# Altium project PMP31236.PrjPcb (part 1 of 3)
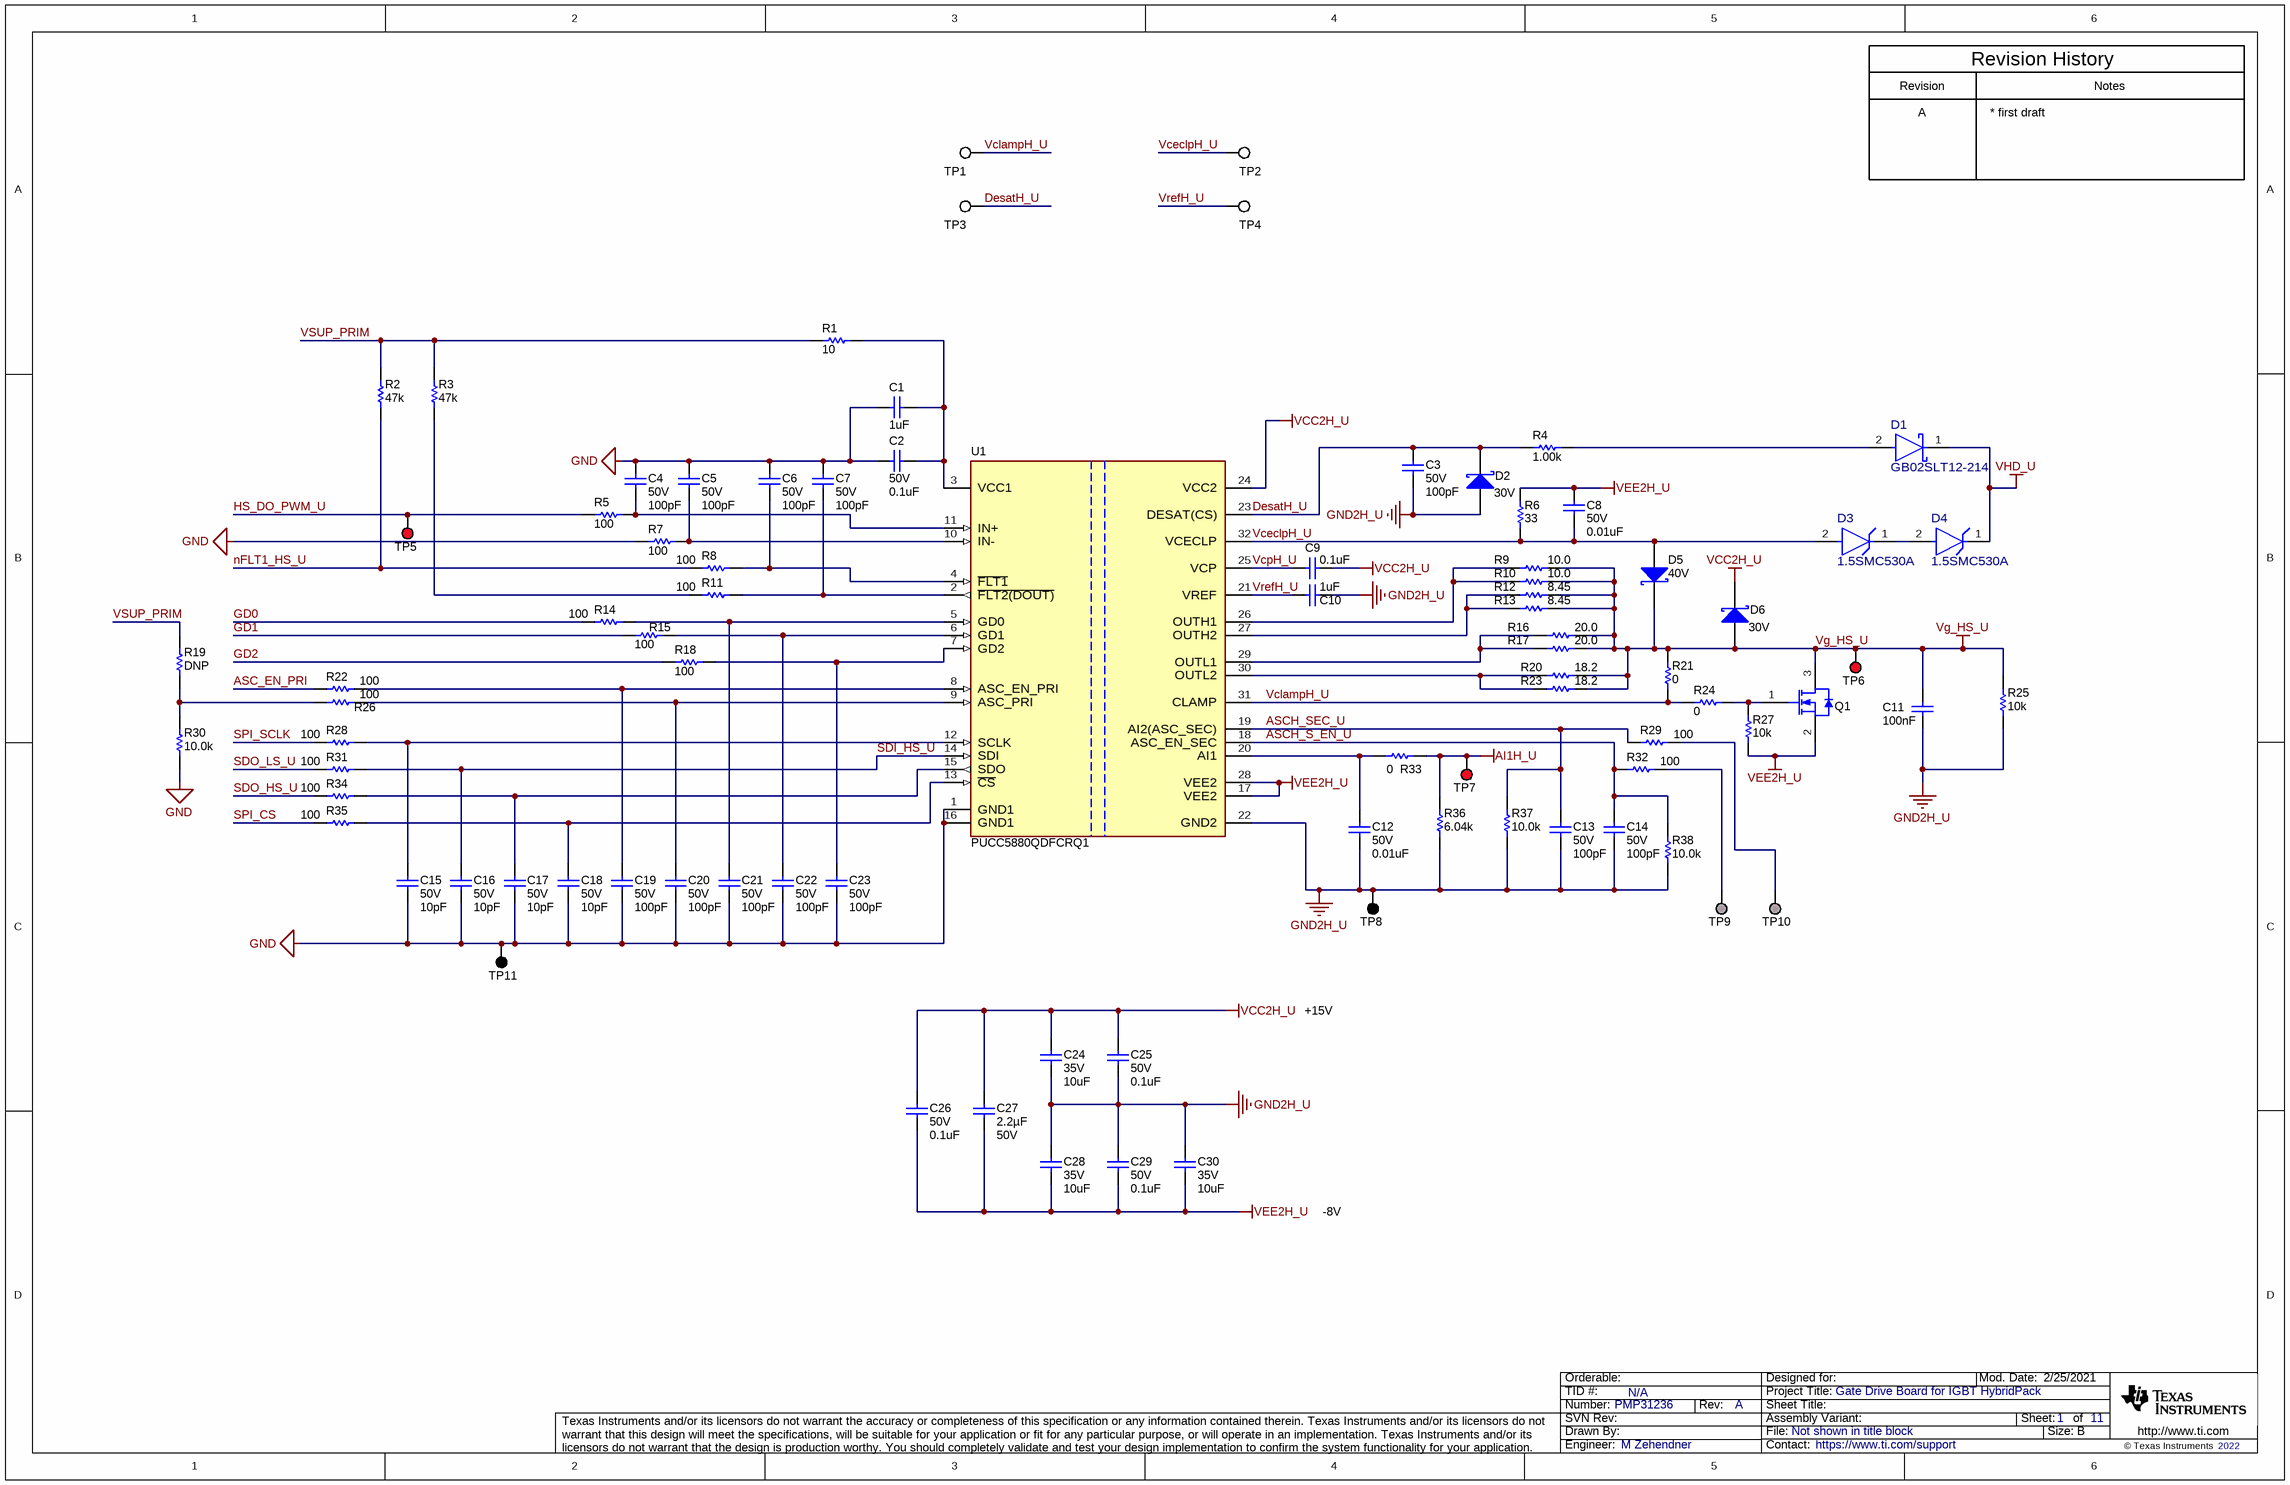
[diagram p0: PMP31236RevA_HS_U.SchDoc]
CopyrightYear: 2022; PRJ_Engineer: M Zehendner; PRJ_Number: PMP31236; PRJ_Title: Gate Drive Board for IGBT HybridPack; SCH_Rev: A; TechSupport: https://www.ti.com/support; TID: N/A
11 sheets, 732 parts. Net scope: global (net labels, ports and power ports of the same name join across sheets).
Board file: PMP31236.PcbDoc
Sheets:
  PMP31236RevA_HS_U.SchDoc
  PMP31236RevA_HS_V.SchDoc
  PMP31236RevA_HS_W.SchDoc
  PMP31236RevA_LS_U.SchDoc
  PMP31236RevA_LS_V.SchDoc
  PMP31236RevA_LS_W.SchDoc
  PMP31236RevA_Interface.SchDoc
  PMP31236RevA_Supply_U.SchDoc
  PMP31236RevA_Supply_V.SchDoc
  PMP31236RevA_Supply_W.SchDoc
  PMP31236RevA_IGBT_Module.SchDoc

## Sheet PMP31236RevA_HS_U.SchDoc
size 431 x 279 mm; Date: Not shown in title block; ApprovedBy: Not shown in title block; CheckedBy: Not shown in title block; Author: Not shown in title block; CompanyName: Not shown in title block; Engineer: Not shown in title block; Organization: Not shown in title block; Address1: Not shown in title block; Address2: Not shown in title block; Address3: Not shown in title block; Address4: Not shown in title block; DocumentNumber: 1; Revision: Use project parameter SCH_Rev; SheetNumber: 1; SheetTotal: 11; PageSetup: Record=PageOptions¦CenterHorizontal=True¦CenterVertical=True¦PrintScale=1.00¦XCorrection=1.00¦YCorrection=1.00¦PrintKind=0¦BorderSize=5000000¦LeftOffset=0¦BottomOffset=0¦Orientation=2¦PaperLength=1000¦PaperWidth=1000¦Scale=100¦PaperSource=15¦PrintQuality=600¦MediaType=1¦DitherType=10¦PaperKind=Letter¦PrintScaleMode=1

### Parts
C1  ValueDisplayed: 1uF  [0603]  (hidden comment: GRM21BR72A104KAC4L)
C2  VDC_V: 50V  ValueDisplayed: 0.1uF  [0402]  (hidden comment: GCM155R71H104KE02D)
C3  VDC_V: 50V  ValueDisplayed: 100pF  [0402]  (hidden comment: GRM1555C1H101JA01D)
C4  VDC_V: 50V  ValueDisplayed: 100pF  [0402]  (hidden comment: GRM1555C1H101JA01D)
C5  VDC_V: 50V  ValueDisplayed: 100pF  [0402]  (hidden comment: GRM1555C1H101JA01D)
C6  VDC_V: 50V  ValueDisplayed: 100pF  [0402]  (hidden comment: GRM1555C1H101JA01D)
C7  VDC_V: 50V  ValueDisplayed: 100pF  [0402]  (hidden comment: GRM1555C1H101JA01D)
C8  VDC_V: 50V  ValueDisplayed: 0.01uF  [0402]  (hidden comment: CGA2B3X7R1H103K050BB)
C9  ValueDisplayed: 0.1uF  [0402]  (hidden comment: GCM155R71H104KE02D)
C10  ValueDisplayed: 1uF  [0603]  (hidden comment: CGA3E1X7R1V105K080AC)
C11  Cap_F: 100nF  [0805_HV]  (hidden comment: C0805C104K5RACAUTO)
C12  VDC_V: 50V  ValueDisplayed: 0.01uF  [0402]  (hidden comment: CGA2B3X7R1H103K050BB)
C13  VDC_V: 50V  ValueDisplayed: 100pF  [0402]  (hidden comment: GRM1555C1H101JA01D)
C14  VDC_V: 50V  ValueDisplayed: 100pF  [0402]  (hidden comment: GRM1555C1H101JA01D)
C15  VDC_V: 50V  ValueDisplayed: 10pF  [0402]  (hidden comment: GCM1555C1H100JA16D)
C16  VDC_V: 50V  ValueDisplayed: 10pF  [0402]  (hidden comment: GCM1555C1H100JA16D)
C17  VDC_V: 50V  ValueDisplayed: 10pF  [0402]  (hidden comment: GCM1555C1H100JA16D)
C18  VDC_V: 50V  ValueDisplayed: 10pF  [0402]  (hidden comment: GCM1555C1H100JA16D)
C19  VDC_V: 50V  ValueDisplayed: 100pF  [0402]  (hidden comment: GRM1555C1H101JA01D)
C20  VDC_V: 50V  ValueDisplayed: 100pF  [0402]  (hidden comment: GRM1555C1H101JA01D)
C21  VDC_V: 50V  ValueDisplayed: 100pF  [0402]  (hidden comment: GRM1555C1H101JA01D)
C22  VDC_V: 50V  ValueDisplayed: 100pF  [0402]  (hidden comment: GRM1555C1H101JA01D)
C23  VDC_V: 50V  ValueDisplayed: 100pF  [0402]  (hidden comment: GRM1555C1H101JA01D)
C24  VDC_V: 35V  ValueDisplayed: 10uF  [1206_190]  (hidden comment: CGA5L1X7R1V106M160AC)
C25  VDC_V: 50V  ValueDisplayed: 0.1uF  [0402]  (hidden comment: GCM155R71H104KE02D)
C26  VDC_V: 50V  ValueDisplayed: 0.1uF  [0402]  (hidden comment: GCM155R71H104KE02D)
C27  Cap_F: 2.2µF  VDC_V: 50V  [0805_HV]  (hidden comment: CGA4J3X7R1H225K125AB)
C28  VDC_V: 35V  ValueDisplayed: 10uF  [1206_190]  (hidden comment: CGA5L1X7R1V106M160AC)
C29  VDC_V: 50V  ValueDisplayed: 0.1uF  [0402]  (hidden comment: GCM155R71H104KE02D)
C30  VDC_V: 35V  ValueDisplayed: 10uF  [1206_190]  (hidden comment: CGA5L1X7R1V106M160AC)
D1  GB02SLT12-214  [FP-GB02SLT12-214_DO-214AA-MFG]
D2  value 30V  [SOD-323]  (hidden comment: BAT54WS-7-F)
D3  1.5SMC530A  [FP-1.5SMC530A_SMC-MFG]
D4  1.5SMC530A  [FP-1.5SMC530A_SMC-MFG]
D5  value 40V  [SMA]  (hidden comment: MBRA340T3G)
D6  value 30V  [SOD-323]  (hidden comment: BAT54WS-7-F)
Q1  SI2318CDS-T1-GE3  [SOT-23]  (value not drawn)
R1  ValueDisplayed: 10  [0402]  (hidden comment: CRCW040210R0JNED)
R2  ValueDisplayed: 47k  [0402]  (hidden comment: CRCW040247K0JNED)
R3  ValueDisplayed: 47k  [0402]  (hidden comment: CRCW040247K0JNED)
R4  ValueDisplayed: 1.00k  [0603]  (hidden comment: CRCW06031K00FKEA)
R5  ValueDisplayed: 100  [0402]  (hidden comment: CRCW0402100RJNED)
R6  ValueDisplayed: 33  [0603]  (hidden comment: CRCW060333R0JNEA)
R7  ValueDisplayed: 100  [0402]  (hidden comment: CRCW0402100RJNED)
R8  ValueDisplayed: 100  [0402]  (hidden comment: CRCW0402100RJNED)
R9  ValueDisplayed: 10.0  [0805_HV]  (hidden comment: CRCW080510R0FKEA)
R10  ValueDisplayed: 10.0  [0805_HV]  (hidden comment: CRCW080510R0FKEA)
R11  ValueDisplayed: 100  [0402]  (hidden comment: CRCW0402100RJNED)
R12  ValueDisplayed: 8.45  [0805_HV]  (hidden comment: CRCW08058R45FKEA)
R13  ValueDisplayed: 8.45  [0805_HV]  (hidden comment: CRCW08058R45FKEA)
R14  ValueDisplayed: 100  [0402]  (hidden comment: CRCW0402100RJNED)
R15  ValueDisplayed: 100  [0402]  (hidden comment: CRCW0402100RJNED)
R16  ValueDisplayed: 20.0  [0805_HV]  (hidden comment: CRCW080520R0FKEA)
R17  ValueDisplayed: 20.0  [0805_HV]  (hidden comment: CRCW080520R0FKEA)
R18  ValueDisplayed: 100  [0402]  (hidden comment: CRCW0402100RJNED)
R19  ValueDisplayed: DNP  [0402]  (hidden comment: CRCW040210K0FKED)
R20  ValueDisplayed: 18.2  [0805_HV]  (hidden comment: CRCW080518R2FKEA)
R21  ValueDisplayed: 0  [0603]  (hidden comment: CRCW06030000Z0EA)
R22  ValueDisplayed: 100  [0402]  (hidden comment: CRCW0402100RJNED)
R23  ValueDisplayed: 18.2  [0805_HV]  (hidden comment: CRCW080518R2FKEA)
R24  ValueDisplayed: 0  [0603]  (hidden comment: CRCW06030000Z0EA)
R25  ValueDisplayed: 10k  [0603]  (hidden comment: CRCW060310K0JNEA)
R26  ValueDisplayed: 100  [0402]  (hidden comment: CRCW0402100RJNED)
R27  ValueDisplayed: 10k  [0603]  (hidden comment: CRCW060310K0JNEA)
R28  ValueDisplayed: 100  [0402]  (hidden comment: CRCW0402100RJNED)
R29  ValueDisplayed: 100  [0402]  (hidden comment: CRCW0402100RFKED)
R30  ValueDisplayed: 10.0k  [0402]  (hidden comment: CRCW040210K0FKED)
R31  ValueDisplayed: 100  [0402]  (hidden comment: CRCW0402100RJNED)
R32  ValueDisplayed: 100  [0402]  (hidden comment: CRCW0402100RFKED)
R33  ValueDisplayed: 0  [0402]  (hidden comment: CRCW04020000Z0ED)
R34  ValueDisplayed: 100  [0402]  (hidden comment: CRCW0402100RJNED)
R35  ValueDisplayed: 100  [0402]  (hidden comment: CRCW0402100RJNED)
R36  ValueDisplayed: 6.04k  [0402]  (hidden comment: CRCW04026K04FKED)
R37  ValueDisplayed: 10.0k  [0402]  (hidden comment: CRCW040210K0FKED)
R38  ValueDisplayed: 10.0k  [0402]  (hidden comment: CRCW040210K0FKED)
TP1  (no value)  [Keystone5002]
TP2  (no value)  [Keystone5002]
TP3  (no value)  [Keystone5002]
TP4  (no value)  [Keystone5002]
TP5  5000  [Keystone5000]  (value not drawn)
TP6  5000  [Keystone5000]  (value not drawn)
TP7  5000  [Keystone5000]  (value not drawn)
TP8  5001  [Keystone5001]  (value not drawn)
TP9  TP_SM_1MM  [TP_SM_1MM]  (value not drawn)  (no BOM)
TP10  TP_SM_1MM  [TP_SM_1MM]  (value not drawn)  (no BOM)
TP11  5001  [Keystone5001]  (value not drawn)
U1  PUCC5880QDFCRQ1  [DFC0032A-MFG]

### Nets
AI1H_U: R33.2 R36.2 TP7.1
GND: C1.2 C2.1 C4.1 C5.1 C6.1 C7.1 C15.2 C16.2 C17.2 C18.2 C19.2 C20.2 C21.2 C22.2 C23.2 R7.1 R30.1 TP11.1 U1.1(GND1) U1.16(GND1)
GND2H_U: C3.2 C10.2 C11.2 C12.2 C13.2 C14.2 C24.2 C25.2 C28.1 C29.1 C30.1 D2.2(A) R25.1 R36.1 R37.1 R38.1 TP8.1 U1.22(GND2)
VCC2H_U: C9.2 C24.1 C25.1 C26.1 C27.1 D6.1(K) U1.24(VCC2)
VEE2H_U: C8.1 C26.2 C27.2 C28.2 C29.2 C30.2 Q1.2(S) R6.2 R27.1 U1.17(VEE2) U1.28(VEE2)
Vg_HS_U: C11.1 D5.1(K) D6.2(A) Q1.3(D) R9.2 R10.2 R12.2 R13.2 R16.2 R17.2 R20.2 R21.2 R23.2 R25.2 TP6.1
VHD_U: D1.1(CATHODE) D4.1(CATHODE)
ASC_EN_PRI: R22.1
ASCH_S_EN_U: C14.1 R32.1 R38.2 U1.18(ASC_EN_SEC)
ASCH_SEC_U: C13.1 R29.1 R37.2 U1.19(AI2(ASC_SEC))
DesatH_U: C3.1 D2.1(K) R4.1 TP3.1 U1.23(DESAT(CS))
GD0: R14.1
GD1: R15.1
GD2: R18.1
HS_DO_PWM_U: R5.1 TP5.1
nFLT1_HS_U: R2.1 R8.1
SDI_HS_U: C16.1 R31.2 U1.14(SDI)
SDO_HS_U: R34.1
SDO_LS_U: R31.1
SPI_CS: R35.1
SPI_SCLK: R28.1
VceclpH_U: C8.2 D3.2(ANODE) D5.2(A) R6.1 TP2.1 U1.32(VCECLP)
VclampH_U: R21.1 R24.2 TP1.1 U1.31(CLAMP)
VcpH_U: C9.1 U1.25(VCP)
VrefH_U: C10.1 TP4.1 U1.21(VREF)
VSUP_PRIM: R1.1 R2.2 R3.2 R19.2
NetC1_1: C1.1 C2.2 R1.2 U1.3(VCC1)
NetC4_2: C4.2 R5.2 U1.11(IN+)
NetC5_2: C5.2 R7.2 U1.10(IN-)
NetC6_2: C6.2 R8.2 U1.4(~{FLT1})
NetC7_2: C7.2 R11.2 U1.2(~{FLT2(DOUT)})
NetC12_1: C12.1 R33.1 U1.20(AI1)
NetC15_1: C15.1 R28.2 U1.12(SCLK)
NetC17_1: C17.1 R34.2 U1.15(SDO)
NetC18_1: C18.1 R35.2 U1.13(~{CS})
NetC19_1: C19.1 R22.2 U1.8(ASC_EN_PRI)
NetC20_1: C20.1 R26.2 U1.9(ASC_PRI)
NetC21_1: C21.1 R14.2 U1.5(GD0)
NetC22_1: C22.1 R15.2 U1.6(GD1)
NetC23_1: C23.1 R18.2 U1.7(GD2)
NetD1_2: D1.2(ANODE) R4.2
NetD3_1: D3.1(CATHODE) D4.2(ANODE)
NetQ1_1: Q1.1(G) R24.1 R27.2
NetR3_1: R3.1 R11.1
NetR9_1: R9.1 R10.1 U1.26(OUTH1)
NetR12_1: R12.1 R13.1 U1.27(OUTH2)
NetR16_1: R16.1 R17.1 U1.29(OUTL1)
NetR19_1: R19.1 R26.1 R30.2
NetR20_1: R20.1 R23.1 U1.30(OUTL2)
NetR29_2: R29.2 TP10.1
NetR32_2: R32.2 TP9.1

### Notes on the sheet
- Revision
- Revision History
- Notes
- A
- * first draft
- +15V
- -8V

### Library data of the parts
C1 = CMP-0007067-4: CAP, CERM, 1 uF, 35 V, +/- 10%, X7R, AEC-Q200 Grade 1, 0603; Manufacturer: TDK; PartNumber: CGA3E1X7R1V105K080AC; TaMin_C: -55°C; ESR_ohm: 5.522m; Polarized: N; SizeAreaWB_mm2: 4.68; Value1: 0.005522 ohm; U/M: EA; Value: 1uF; TaMax_C: 125°C; SizeZ_mm: 1; SizeX_mm: 1.6; SizeY_mm: 0.8; Value2: 35V; SizeArea_mm2: 1.28; CompType: Capacitor; AEC Qualified: Y; Cap_F: 1µF; IRMS_A: 2.21617A; AEC Category: Q200
C2 C25 C26 C29 = CMP-0006356-2: CAP, CERM, 0.1 uF, 50 V, +/- 10%, X7R, AEC-Q200 Grade 1, 0402; Manufacturer: MuRata; TaMin_C: -55°C; Polarized: N; SizeAreaWB_mm2: 3; Value1: Unknown; U/M: EA; Value: 0.1uF; TaMax_C: 125°C; SizeZ_mm: 0.6; SizeX_mm: 1; SizeY_mm: 0.5; AEC Qualified: Y; Cap_F: 100nF; AEC Category: Q200
C3-C7 C13 C14 C19-C23 = CMP-0006410-2: CAP, CERM, 100 pF, 50 V, +/- 5%, C0G/NP0, 0402; Manufacturer: MuRata; TaMin_C: -55°C; Polarized: N; SizeAreaWB_mm2: 3; Value1: Unknown; U/M: EA; Value: 100pF; TaMax_C: 125°C; SizeZ_mm: 0.6; SizeX_mm: 1; SizeY_mm: 0.5; AEC Category: Q200
C8 C12 = CMP-0006324-2: CAP, CERM, 0.01 uF, 50 V, +/- 10%, X7R, AEC-Q200 Grade 1, 0402; Manufacturer: TDK; TaMin_C: -55°C; ESR_ohm: 0.3331; Polarized: N; SizeAreaWB_mm2: 3; Value1: 0.333065 ohm; U/M: EA; Value: 0.01uF; TaMax_C: 125°C; SizeZ_mm: 0.6; SizeX_mm: 1; SizeY_mm: 0.5; AEC Qualified: Y; Cap_F: 10nF; IRMS_A: 323.373mA; AEC Category: Q200
C9 = CMP-0006356-2: CAP, CERM, 0.1 uF, 50 V, +/- 10%, X7R, AEC-Q200 Grade 1, 0402; Manufacturer: MuRata; TaMin_C: -55°C; Polarized: N; SizeAreaWB_mm2: 3; Value1: Unknown; U/M: EA; Value: 0.1uF; TaMax_C: 125°C; SizeZ_mm: 0.6; SizeX_mm: 1; SizeY_mm: 0.5; Value2: 50V; AEC Qualified: Y; Cap_F: 100nF; AEC Category: Q200
C10 = CMP-0007067-4: CAP, CERM, 1 uF, 35 V, +/- 10%, X7R, AEC-Q200 Grade 1, 0603; Manufacturer: TDK; TaMin_C: -55°C; ESR_ohm: 5.522m; Polarized: N; SizeAreaWB_mm2: 4.68; Value1: 0.005522 ohm; U/M: EA; Value: 1uF; TaMax_C: 125°C; SizeZ_mm: 1; SizeX_mm: 1.6; SizeY_mm: 0.8; Value2: 35V; SizeArea_mm2: 1.28; CompType: Capacitor; AEC Qualified: Y; Cap_F: 1µF; IRMS_A: 2.21617A; AEC Category: Q200
C11 = CMP-0007725-2: CAP, CERM, 0.1 uF, 50 V, +/- 10%, X7R, AEC-Q200 Grade 0, 0805; Manufacturer: Kemet; TaMin_C: -55°C; Polarized: N; SizeAreaWB_mm2: 6.75; Value1: Unknown; U/M: EA; Value: 0.1uF; TaMax_C: 125°C; SizeZ_mm: 1.45; SizeX_mm: 2; SizeY_mm: 1.25; Cap_Case: 0805; Value2: 50V; SizeArea_mm2: 2.5; AEC Qualified: Y; AEC Grade: 0; AEC Category: Q200
C15-C18 = CMP-0860290-1: CAP, CERM, 10 pF, 50 V,+/- 5%, C0G/NP0, AEC-Q200 Grade 1, 0402; Manufacturer: MuRata; TaMin_C: -55°C; AEC Grade: 1; AEC Qualified: Y; SizeAreaWB_mm2: 3; SizeZ_mm: 0.6; Value: 10pF; TaMax_C: 125°C; Polarized: N; SizeArea_mm2: 0.5; U/M: EA; AEC Category: Q200
C24 C28 C30 = CMP-0008772-2: CAP, CERM, 10 uF, 35 V, +/- 10%, X7R, AEC-Q200 Grade 1, 1206_190; Manufacturer: TDK; PartNumber: CGA5L1X7R1V106K160AC; TaMin_C: -55°C; ESR_ohm: 2.229m; Polarized: N; SizeAreaWB_mm2: 10.92; Value1: 0.002229 ohm; U/M: EA; Value: 10uF; TaMax_C: 125°C; SizeZ_mm: 1.9; SizeX_mm: 3.2; SizeY_mm: 1.6; SizeArea_mm2: 5.12; AEC Qualified: Y; Cap_F: 10µF; IRMS_A: 4.85932A; AEC Grade: 1; AEC Category: Q200
C27 = CMP-0007977-2: CAP, CERM, 2.2 uF, 50 V, +/- 10%, X7R, AEC-Q200 Grade 1, 0805; Manufacturer: TDK; TaMin_C: -55°C; ESR_ohm: 3.288m; Polarized: N; SizeAreaWB_mm2: 6.75; Value1: 0.003288 ohm; U/M: EA; Value: 2.2uF; TaMax_C: 125°C; SizeZ_mm: 1.45; SizeX_mm: 2; SizeY_mm: 1.25; Cap_Case: 0805; SizeArea_mm2: 2.5; AEC Qualified: Y; IRMS_A: 3.6003A; AEC Grade: 1; AEC Category: Q200
D1 = CMP-0095009-1: Diode Silicon Carbide Schottky 1200 V 2A (DC) Surface Mount DO-214AA; Manufacturer: GeneSiC Semiconductor; Max Surge Forward Current: 20A; ValueDisplayed: 122pF; Vf_V: 1.2kV; Peak Reverse Current: 1uA; SizeZ_mm: 2.44mm; AEC Qualified: No; TJmax_C: 175°C
D2 D6 = CMP-0028458-1: Diode, Schottky, 30 V, 0.2 A, SOD-323; Manufacturer: Diodes Inc.; Io_A: 2dA; Green_Lifecycle: Active; SizeAreaWB_mm2: 8.695; Green_REACh: Passed; Value1: 0.2A; TJmax_C: 125°C; U/M: EA; SizeZ_mm: 1; SizeX_mm: 2.7; SizeY_mm: 1.35; Vf_V: 7dV; Value2: 0.7V; SizeArea_mm2: 3.645; AEC Category: Q101
D3 D4 = CMP-0095023-1: 725V Clamp 2.1A Ipp Tvs Diode Surface Mount DO-214AB (SMCJ); Manufacturer: Littelfuse Inc; SizeZ_mm: 2.62mm; Breakdown Voltage: 503.5V; Ppk: 1.5kW; VRWM: 451V; Direction: Unidirectional; AEC Qualified: No; TJmax_C: +150°C; Number Of Channels: 1; Ipp: 2.8A
D5 = CMP-0028553-2: Diode, Schottky, 40 V, 3 A, SMA; Manufacturer: ON Semiconductor; Io_A: 3A; Green_Lifecycle: Not Set; SizeAreaWB_mm2: 37.3428; Green_REACh: Incomplete; SizeZ_mm: 2.87; SizeX_mm: 5.59; SizeY_mm: 2.92; Vf_V: 415mV; Value2: 0.415V; SizeArea_mm2: 16.3228; AEC Category: Q101; RJC_CperW: 15
Q1 = CMP-0000739-1: MOSFET, N-CH, 40 V, 5.6 A, SOT-23; Alternate Manufacturer: None; Manufacturer: Vishay-Siliconix; SizeZ_mm: 1.1; ChType: N; Value2: 5.8 nC; Value1: 0.05; VdsMax_V: 40V; SizeX_mm: 2.5; SizeY_mm: 3; Vgs_V: 20V; Value: 40V; Rdson45_ohm: 0.051; SizeArea_mm2: 7.5; AEC Category: Q101; IdsMax_A: 5.6A; SizeAreaWB_mm2: 14; U/M: EA; QgTyp_nC: 5.8
R1 = CMP-0026827-3: RES, 10, 5%, 0.063 W, AEC-Q200 Grade 0, 0402; Manufacturer: Vishay-Dale; Power_W: 63mW; TempCo: 200 ppm/C; Value_Code: 10R0; Value: 10; EIA_Code: E24; SizeX_mm: 1; SizeY_mm: 0.5; SizeZ_mm: 0.6; Value2: 0.063W; AEC Qualified: Y; VDC_V: 50V; AEC Category: Q200; AEC Grade: 0
R2 R3 = CMP-0026935-3: RES, 47 k, 5%, 0.063 W, AEC-Q200 Grade 0, 0402; Manufacturer: Vishay-Dale; Power_W: 63mW; TempCo: 200 ppm/C; Value_Code: 47k0; Value: 47k; EIA_Code: E24; SizeX_mm: 1; SizeY_mm: 0.5; SizeZ_mm: 0.6; Value2: 0.063W; AEC Qualified: Y; VDC_V: 50V; AEC Category: Q200; AEC Grade: 0
R4 = CMP-0022109-5: RES, 1.00 k, 1%, 0.1 W, AEC-Q200 Grade 0, 0603; Manufacturer: Vishay-Dale; Power_W: 100mW; TempCo: 100 ppm/C; Value_Code: 1k00; Value: 1.00k; EIA_Code: E96; Res_ohm: 1k; SizeX_mm: 1.6; SizeY_mm: 0.8; SizeZ_mm: 1; Value2: 0.1W; SizeArea_mm2: 1.28; AEC Qualified: Y; VDC_V: 75V; AEC Category: Q200; AEC Grade: 0
R5 R7 R8 R11 R14 R15 R18 R22 R26 R28 R31 R34 R35 = CMP-0026824-2: RES, 100, 5%, 0.063 W, 0402; Manufacturer: Vishay-Dale; Power_W: 63mW; TempCo: 200 ppm/C; Value_Code: 100R; U/M: EA; Value: 100; EIA_Code: E24; SizeX_mm: 1; SizeY_mm: 0.5; SizeZ_mm: 0.6; Value2: 0.063W; VDC_V: 50V; AEC Category: Q200
R6 = CMP-0025787-4: RES, 33, 5%, 0.1 W, AEC-Q200 Grade 0, 0603; Manufacturer: Vishay-Dale; Power_W: 100mW; TempCo: 200 ppm/C; Value_Code: 33R0; Value: 33; EIA_Code: E24; SizeX_mm: 1.6; SizeY_mm: 0.8; SizeZ_mm: 1; Value2: 0.1W; SizeArea_mm2: 1.28; CompType: Resistor; AEC Qualified: Y; VDC_V: 75V; AEC Category: Q200; AEC Grade: 0
R9 R10 = CMP-0020847-3: RES, 10.0, 1%, 0.125 W, AEC-Q200 Grade 0, 0805; Manufacturer: Vishay-Dale; Power_W: 125mW; TempCo: 100 ppm/C; Value_Code: 10R0; Value: 10.0; EIA_Code: E96; Res_ohm: 10; SizeX_mm: 2; SizeY_mm: 1.25; SizeZ_mm: 1.45; Value2: 0.125W; SizeArea_mm2: 2.5; AEC Qualified: Y; VDC_V: 150V; AEC Category: Q200; AEC Grade: 0
R12 R13 = CMP-0021481-3: RES, 8.45, 1%, 0.125 W, AEC-Q200 Grade 0, 0805; Manufacturer: Vishay-Dale; Power_W: 125mW; TempCo: 100 ppm/C; Value_Code: 8R45; Value: 8.45; EIA_Code: E96; SizeX_mm: 2; SizeY_mm: 1.25; SizeZ_mm: 1.45; Value2: 0.125W; SizeArea_mm2: 2.5; AEC Qualified: Y; VDC_V: 150V; AEC Category: Q200; AEC Grade: 0
R16 R17 = CMP-0021044-3: RES, 20.0, 1%, 0.125 W, AEC-Q200 Grade 0, 0805; Manufacturer: Vishay-Dale; Power_W: 125mW; Value_Code: 20R0; TempCo: 100 ppm/C; Value: 20.0; EIA_Code: E96; Res_ohm: 20; SizeX_mm: 2; SizeY_mm: 1.25; SizeZ_mm: 1.45; Value2: 0.125W; SizeArea_mm2: 2.5; AEC Qualified: Y; VDC_V: 150V; AEC Category: Q200; AEC Grade: 0
R19 R30 R37 R38 = CMP-0025958-3: RES, 10.0 k, 1%, 0.063 W, AEC-Q200 Grade 0, 0402; Manufacturer: Vishay-Dale; Power_W: 63mW; TempCo: 100 ppm/C; Value_Code: 10k0; Value: 10.0k; EIA_Code: E96; Res_ohm: 10k; SizeX_mm: 1; SizeY_mm: 0.5; SizeZ_mm: 0.6; Value2: 0.063W; AEC Qualified: Y; VDC_V: 50V; AEC Category: Q200; AEC Grade: 0
R20 R23 = CMP-0020941-3: RES, 18.2, 1%, 0.125 W, AEC-Q200 Grade 0, 0805; Manufacturer: Vishay-Dale; Power_W: 125mW; TempCo: 100 ppm/C; Value_Code: 18R2; Value: 18.2; EIA_Code: E96; SizeX_mm: 2; SizeY_mm: 1.25; SizeZ_mm: 1.45; Value2: 0.125W; SizeArea_mm2: 2.5; AEC Qualified: Y; VDC_V: 150V; AEC Category: Q200; AEC Grade: 0
R21 R24 = CMP-0025697-4: RES, 0, 5%, 0.1 W, AEC-Q200 Grade 0, 0603; Manufacturer: Vishay-Dale; Power_W: 100mW; TempCo: 200 ppm/C; Value_Code: 0000; Value: 0; EIA_Code: E24; SizeX_mm: 1.6; SizeY_mm: 0.8; SizeZ_mm: 1; Value2: 0.1W; SizeArea_mm2: 1.28; AEC Qualified: Y; VDC_V: 75V; AEC Category: Q200
R25 = CMP-0025701-4: RES, 10 k, 5%, 0.1 W, AEC-Q200 Grade 0, 0603; Manufacturer: Vishay-Dale; Power_W: 100mW; TempCo: 200 ppm/C; Value_Code: 10k0; Value: 10k; EIA_Code: E24; SizeX_mm: 1.6; SizeY_mm: 0.8; SizeZ_mm: 1; Value2: 0.1W; SizeArea_mm2: 1.28; AEC Qualified: Y; VDC_V: 75V; AEC Category: Q200; AEC Grade: 0
R27 = CMP-0025701-4: RES, 10 k, 5%, 0.1 W, AEC-Q200 Grade 0, 0603; Manufacturer: Vishay-Dale; Power_W: 100mW; TempCo: 200 ppm/C; Value_Code: 10k0; Value: 10k; EIA_Code: E24; SizeX_mm: 1.6; SizeY_mm: 0.8; SizeZ_mm: 1; Value2: 0.1W; SizeArea_mm2: 1.28; CompType: Resistor; AEC Qualified: Y; VDC_V: 75V; AEC Category: Q200; AEC Grade: 0
R29 R32 = CMP-0025951-3: RES, 100, 1%, 0.063 W, AEC-Q200 Grade 0, 0402; Manufacturer: Vishay-Dale; Power_W: 63mW; TempCo: 100 ppm/C; Value_Code: 100R; Value: 100; EIA_Code: E96; SizeX_mm: 1; SizeY_mm: 0.5; SizeZ_mm: 0.6; Value2: 0.063W; AEC Qualified: Y; VDC_V: 50V; AEC Category: Q200; AEC Grade: 0
R33 = CMP-0026822-3: RES, 0, 5%, 0.063 W, AEC-Q200 Grade 0, 0402; Manufacturer: Vishay-Dale; Power_W: 63mW; TempCo: 200 ppm/C; Value_Code: 0000; Value: 0; EIA_Code: E24; SizeX_mm: 1; SizeY_mm: 0.5; SizeZ_mm: 0.6; Value2: 0.063W; AEC Qualified: Y; VDC_V: 50V; AEC Category: Q200
R36 = CMP-0026512-2: RES, 6.04 k, 1%, 0.063 W, AEC-Q200 Grade 0, 0402; Manufacturer: Vishay-Dale; Power_W: 63mW; TempCo: 100 ppm/C; Value_Code: 6k04; Value: 6.04k; EIA_Code: E96; SizeX_mm: 1; SizeY_mm: 0.5; SizeZ_mm: 0.6; Value2: 0.063W; AEC Qualified: Y; VDC_V: 50V; AEC Category: Q200; AEC Grade: 0
TP1-TP4 = CMP-0055139-1: Test Point, Miniature, White, TH; Manufacturer: Keystone; CNHeader: FALSE; Green_Lifecycle: Active; Green_REACh: Passed; ContactFinish: Silver; CT: TRUE
TP5-TP7 = CMP-0055137-1: Test Point, Miniature, Red, TH; Manufacturer: Keystone; CNHeader: FALSE; Green_Lifecycle: Active; Green_REACh: Passed; ContactFinish: Silver; CT: TRUE
TP8 TP11 = CMP-0055138-1: Test Point, Miniature, Black, TH; Manufacturer: Keystone; CNHeader: FALSE; Green_Lifecycle: Active; Green_REACh: Passed; ContactFinish: Silver; CT: TRUE
TP9 TP10 = CMP-0003825-1: 1mm Test Point, SMT; Manufacturer: Any
U1 = CMP-0093805-2: Isolated 20-A Adjustable Gate Drive Igbt/Sic Mosfet Gate Driver With Advanced Protection Features For Automotive Applications; Manufacturer: Texas Instruments; Nominal Supply Current: 6.5-15mA; TaMax_C: +125°C; TaMin_C: -40°C; AEC Category: Q200; Rise Time: 55ns; Standoff Height: 0.1mm; Number Of Outputs: 2; AEC Grade: Grade 0; TJmax_C: +150°C; Propagation Delay: 150ns; Max Supply Voltage: 30V; Number Of Drivers: 1; SizeZ_mm: 2.65mm; Min Supply Voltage: 3V; AEC Qualified: Yes; CompType: IC

## Sheet PMP31236RevA_HS_V.SchDoc
size 431 x 279 mm; Date: Not shown in title block; ApprovedBy: Not shown in title block; CheckedBy: Not shown in title block; Author: Not shown in title block; CompanyName: Not shown in title block; Engineer: Not shown in title block; Organization: Not shown in title block; Address1: Not shown in title block; Address2: Not shown in title block; Address3: Not shown in title block; Address4: Not shown in title block; DocumentNumber: 2; Revision: Use project parameter SCH_Rev; SheetNumber: 2; SheetTotal: 11; PageSetup: Record=PageOptions¦CenterHorizontal=True¦CenterVertical=True¦PrintScale=1.00¦XCorrection=1.00¦YCorrection=1.00¦PrintKind=0¦BorderSize=5000000¦LeftOffset=0¦BottomOffset=0¦Orientation=2¦PaperLength=1000¦PaperWidth=1000¦Scale=100¦PaperSource=15¦PrintQuality=600¦MediaType=1¦DitherType=10¦PaperKind=Letter¦PrintScaleMode=1
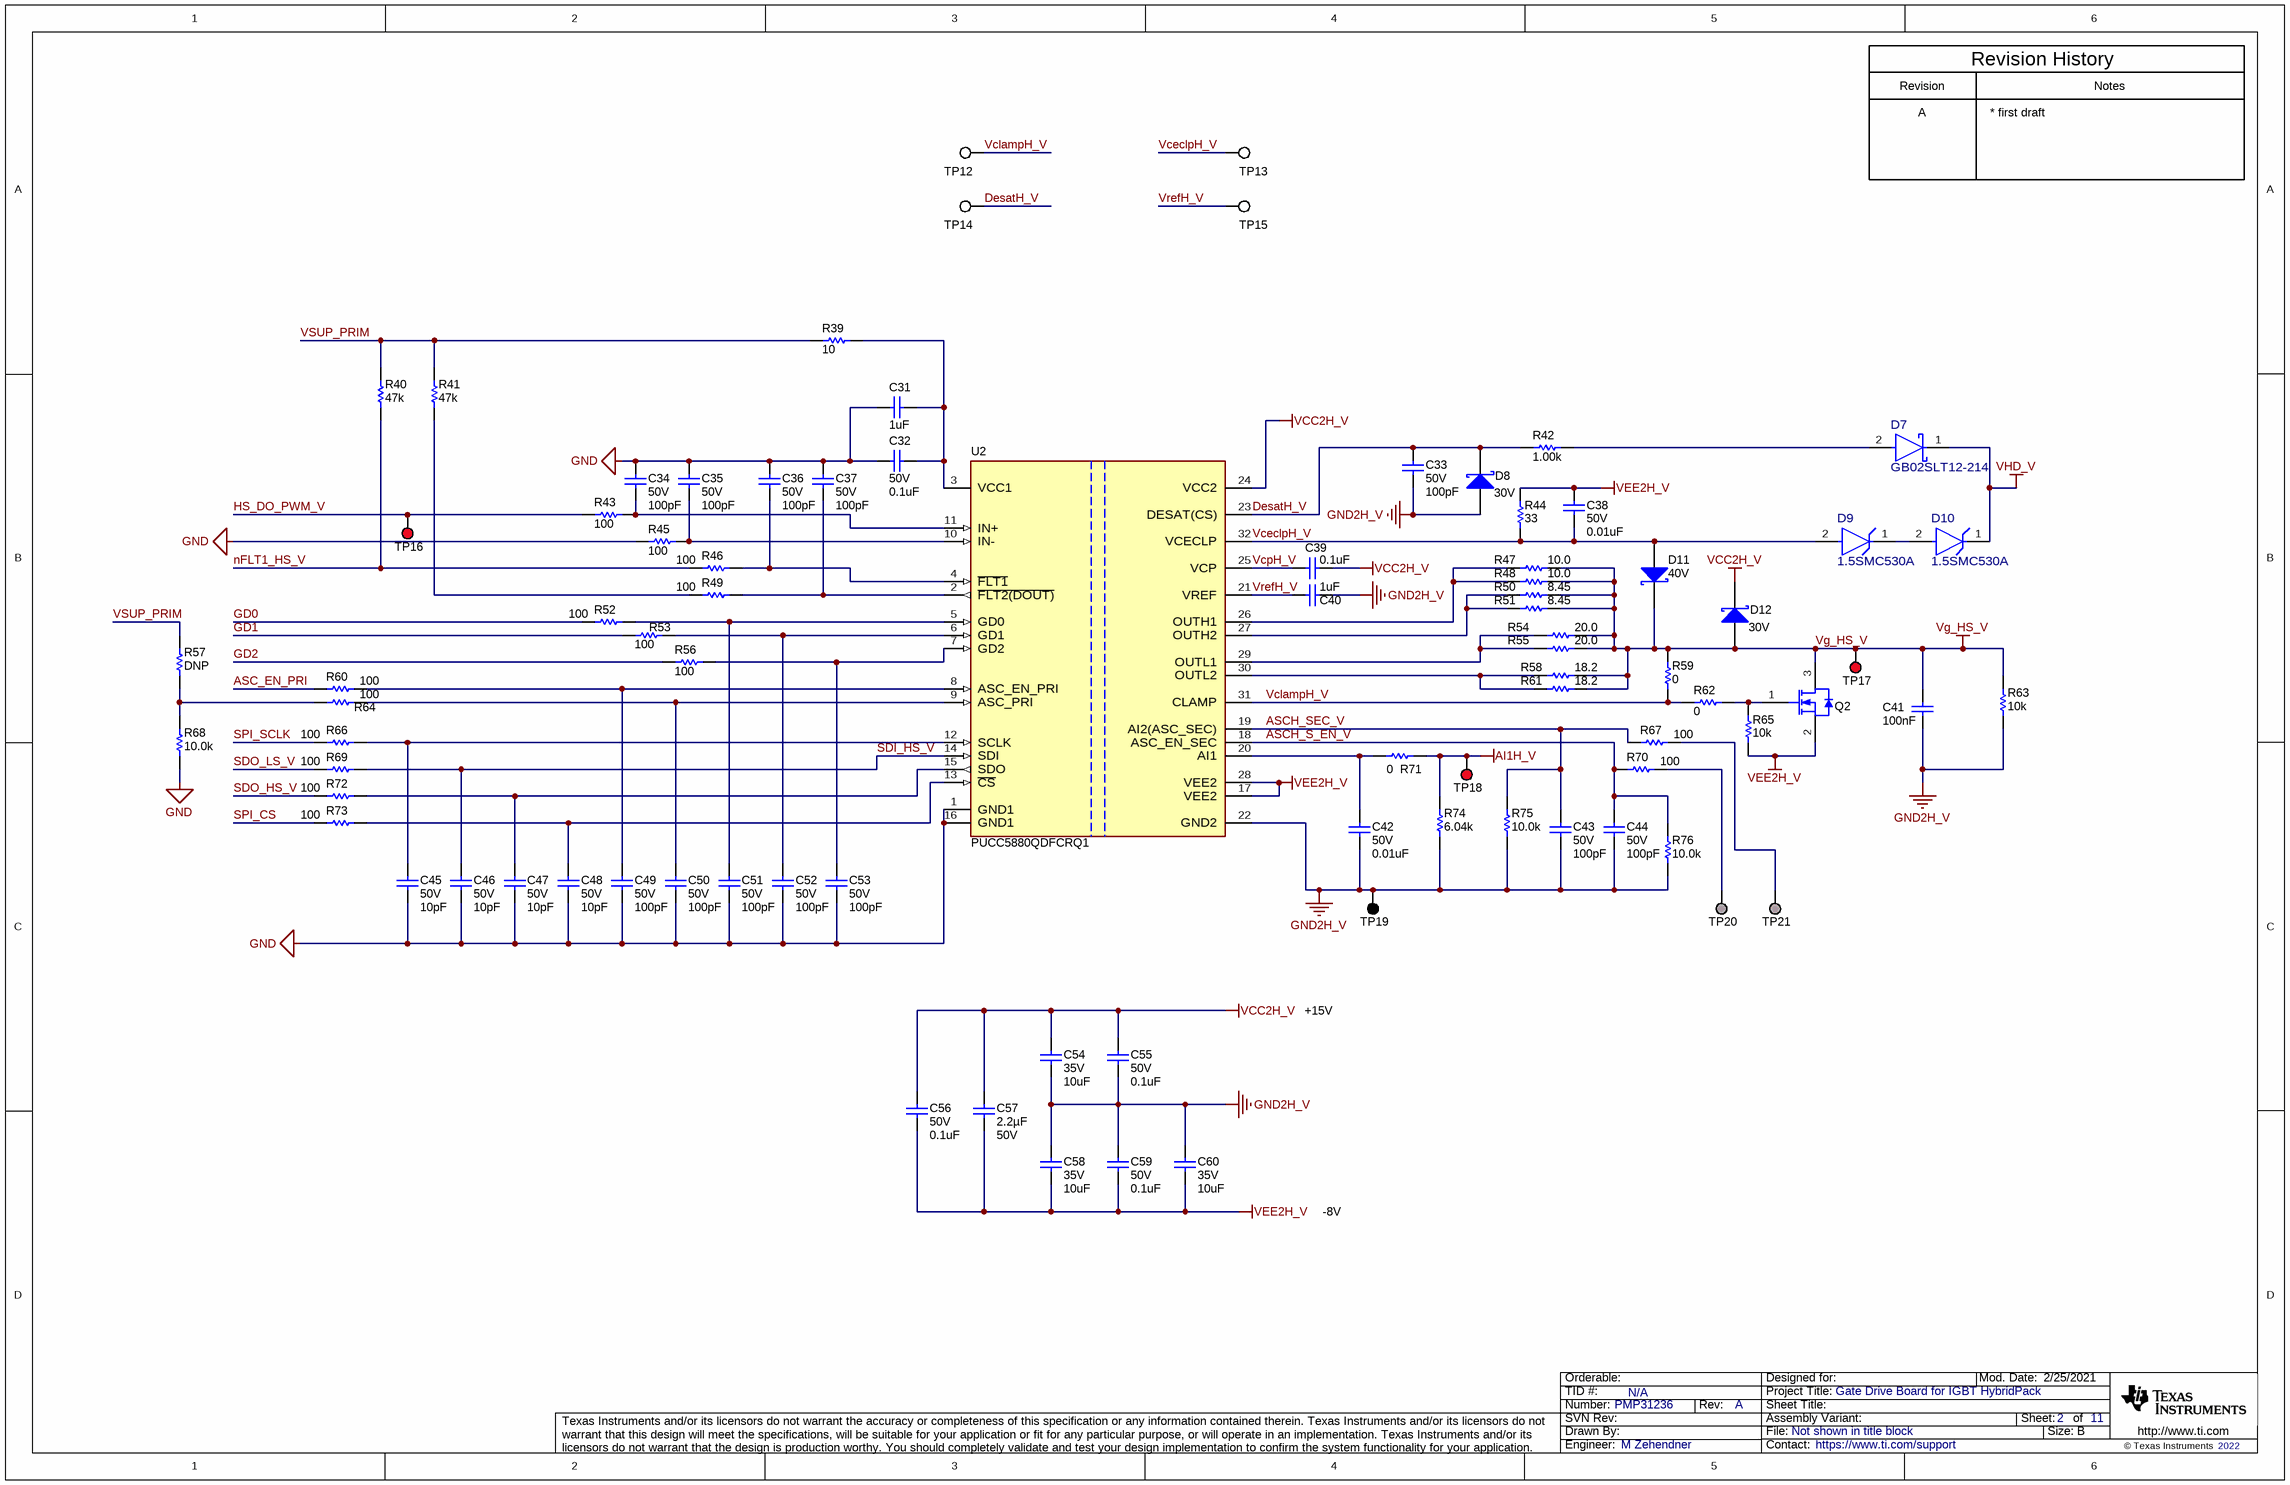
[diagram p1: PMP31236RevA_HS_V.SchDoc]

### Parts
C31  ValueDisplayed: 1uF  [0603]  (hidden comment: GRM21BR72A104KAC4L)
C32  VDC_V: 50V  ValueDisplayed: 0.1uF  [0402]  (hidden comment: GCM155R71H104KE02D)
C33  VDC_V: 50V  ValueDisplayed: 100pF  [0402]  (hidden comment: GRM1555C1H101JA01D)
C34  VDC_V: 50V  ValueDisplayed: 100pF  [0402]  (hidden comment: GRM1555C1H101JA01D)
C35  VDC_V: 50V  ValueDisplayed: 100pF  [0402]  (hidden comment: GRM1555C1H101JA01D)
C36  VDC_V: 50V  ValueDisplayed: 100pF  [0402]  (hidden comment: GRM1555C1H101JA01D)
C37  VDC_V: 50V  ValueDisplayed: 100pF  [0402]  (hidden comment: GRM1555C1H101JA01D)
C38  VDC_V: 50V  ValueDisplayed: 0.01uF  [0402]  (hidden comment: CGA2B3X7R1H103K050BB)
C39  ValueDisplayed: 0.1uF  [0402]  (hidden comment: GCM155R71H104KE02D)
C40  ValueDisplayed: 1uF  [0603]  (hidden comment: CGA3E1X7R1V105K080AC)
C41  Cap_F: 100nF  [0805_HV]  (hidden comment: C0805C104K5RACAUTO)
C42  VDC_V: 50V  ValueDisplayed: 0.01uF  [0402]  (hidden comment: CGA2B3X7R1H103K050BB)
C43  VDC_V: 50V  ValueDisplayed: 100pF  [0402]  (hidden comment: GRM1555C1H101JA01D)
C44  VDC_V: 50V  ValueDisplayed: 100pF  [0402]  (hidden comment: GRM1555C1H101JA01D)
C45  VDC_V: 50V  ValueDisplayed: 10pF  [0402]  (hidden comment: GCM1555C1H100JA16D)
C46  VDC_V: 50V  ValueDisplayed: 10pF  [0402]  (hidden comment: GCM1555C1H100JA16D)
C47  VDC_V: 50V  ValueDisplayed: 10pF  [0402]  (hidden comment: GCM1555C1H100JA16D)
C48  VDC_V: 50V  ValueDisplayed: 10pF  [0402]  (hidden comment: GCM1555C1H100JA16D)
C49  VDC_V: 50V  ValueDisplayed: 100pF  [0402]  (hidden comment: GRM1555C1H101JA01D)
C50  VDC_V: 50V  ValueDisplayed: 100pF  [0402]  (hidden comment: GRM1555C1H101JA01D)
C51  VDC_V: 50V  ValueDisplayed: 100pF  [0402]  (hidden comment: GRM1555C1H101JA01D)
C52  VDC_V: 50V  ValueDisplayed: 100pF  [0402]  (hidden comment: GRM1555C1H101JA01D)
C53  VDC_V: 50V  ValueDisplayed: 100pF  [0402]  (hidden comment: GRM1555C1H101JA01D)
C54  VDC_V: 35V  ValueDisplayed: 10uF  [1206_190]  (hidden comment: CGA5L1X7R1V106M160AC)
C55  VDC_V: 50V  ValueDisplayed: 0.1uF  [0402]  (hidden comment: GCM155R71H104KE02D)
C56  VDC_V: 50V  ValueDisplayed: 0.1uF  [0402]  (hidden comment: GCM155R71H104KE02D)
C57  Cap_F: 2.2µF  VDC_V: 50V  [0805_HV]  (hidden comment: CGA4J3X7R1H225K125AB)
C58  VDC_V: 35V  ValueDisplayed: 10uF  [1206_190]  (hidden comment: CGA5L1X7R1V106M160AC)
C59  VDC_V: 50V  ValueDisplayed: 0.1uF  [0402]  (hidden comment: GCM155R71H104KE02D)
C60  VDC_V: 35V  ValueDisplayed: 10uF  [1206_190]  (hidden comment: CGA5L1X7R1V106M160AC)
D7  GB02SLT12-214  [FP-GB02SLT12-214_DO-214AA-MFG]
D8  value 30V  [SOD-323]  (hidden comment: BAT54WS-7-F)
D9  1.5SMC530A  [FP-1.5SMC530A_SMC-MFG]
D10  1.5SMC530A  [FP-1.5SMC530A_SMC-MFG]
D11  value 40V  [SMA]  (hidden comment: MBRA340T3G)
D12  value 30V  [SOD-323]  (hidden comment: BAT54WS-7-F)
Q2  SI2318CDS-T1-GE3  [SOT-23]  (value not drawn)
R39  ValueDisplayed: 10  [0402]  (hidden comment: CRCW040210R0JNED)
R40  ValueDisplayed: 47k  [0402]  (hidden comment: CRCW040247K0JNED)
R41  ValueDisplayed: 47k  [0402]  (hidden comment: CRCW040247K0JNED)
R42  ValueDisplayed: 1.00k  [0603]  (hidden comment: CRCW06031K00FKEA)
R43  ValueDisplayed: 100  [0402]  (hidden comment: CRCW0402100RJNED)
R44  ValueDisplayed: 33  [0603]  (hidden comment: CRCW060333R0JNEA)
R45  ValueDisplayed: 100  [0402]  (hidden comment: CRCW0402100RJNED)
R46  ValueDisplayed: 100  [0402]  (hidden comment: CRCW0402100RJNED)
R47  ValueDisplayed: 10.0  [0805_HV]  (hidden comment: CRCW080510R0FKEA)
R48  ValueDisplayed: 10.0  [0805_HV]  (hidden comment: CRCW080510R0FKEA)
R49  ValueDisplayed: 100  [0402]  (hidden comment: CRCW0402100RJNED)
R50  ValueDisplayed: 8.45  [0805_HV]  (hidden comment: CRCW08058R45FKEA)
R51  ValueDisplayed: 8.45  [0805_HV]  (hidden comment: CRCW08058R45FKEA)
R52  ValueDisplayed: 100  [0402]  (hidden comment: CRCW0402100RJNED)
R53  ValueDisplayed: 100  [0402]  (hidden comment: CRCW0402100RJNED)
R54  ValueDisplayed: 20.0  [0805_HV]  (hidden comment: CRCW080520R0FKEA)
R55  ValueDisplayed: 20.0  [0805_HV]  (hidden comment: CRCW080520R0FKEA)
R56  ValueDisplayed: 100  [0402]  (hidden comment: CRCW0402100RJNED)
R57  ValueDisplayed: DNP  [0402]  (hidden comment: CRCW040210K0FKED)
R58  ValueDisplayed: 18.2  [0805_HV]  (hidden comment: CRCW080518R2FKEA)
R59  ValueDisplayed: 0  [0603]  (hidden comment: CRCW06030000Z0EA)
R60  ValueDisplayed: 100  [0402]  (hidden comment: CRCW0402100RJNED)
R61  ValueDisplayed: 18.2  [0805_HV]  (hidden comment: CRCW080518R2FKEA)
R62  ValueDisplayed: 0  [0603]  (hidden comment: CRCW06030000Z0EA)
R63  ValueDisplayed: 10k  [0603]  (hidden comment: CRCW060310K0JNEA)
R64  ValueDisplayed: 100  [0402]  (hidden comment: CRCW0402100RJNED)
R65  ValueDisplayed: 10k  [0603]  (hidden comment: CRCW060310K0JNEA)
R66  ValueDisplayed: 100  [0402]  (hidden comment: CRCW0402100RJNED)
R67  ValueDisplayed: 100  [0402]  (hidden comment: CRCW0402100RFKED)
R68  ValueDisplayed: 10.0k  [0402]  (hidden comment: CRCW040210K0FKED)
R69  ValueDisplayed: 100  [0402]  (hidden comment: CRCW0402100RJNED)
R70  ValueDisplayed: 100  [0402]  (hidden comment: CRCW0402100RFKED)
R71  ValueDisplayed: 0  [0402]  (hidden comment: CRCW04020000Z0ED)
R72  ValueDisplayed: 100  [0402]  (hidden comment: CRCW0402100RJNED)
R73  ValueDisplayed: 100  [0402]  (hidden comment: CRCW0402100RJNED)
R74  ValueDisplayed: 6.04k  [0402]  (hidden comment: CRCW04026K04FKED)
R75  ValueDisplayed: 10.0k  [0402]  (hidden comment: CRCW040210K0FKED)
R76  ValueDisplayed: 10.0k  [0402]  (hidden comment: CRCW040210K0FKED)
TP12  (no value)  [Keystone5002]
TP13  (no value)  [Keystone5002]
TP14  (no value)  [Keystone5002]
TP15  (no value)  [Keystone5002]
TP16  5000  [Keystone5000]  (value not drawn)
TP17  5000  [Keystone5000]  (value not drawn)
TP18  5000  [Keystone5000]  (value not drawn)
TP19  5001  [Keystone5001]  (value not drawn)
TP20  TP_SM_1MM  [TP_SM_1MM]  (value not drawn)  (no BOM)
TP21  TP_SM_1MM  [TP_SM_1MM]  (value not drawn)  (no BOM)
U2  PUCC5880QDFCRQ1  [DFC0032A-MFG]

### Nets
AI1H_V: R71.2 R74.2 TP18.1
GND: C31.2 C32.1 C34.1 C35.1 C36.1 C37.1 C45.2 C46.2 C47.2 C48.2 C49.2 C50.2 C51.2 C52.2 C53.2 R45.1 R68.1 U2.1(GND1) U2.16(GND1)
GND2H_V: C33.2 C40.2 C41.2 C42.2 C43.2 C44.2 C54.2 C55.2 C58.1 C59.1 C60.1 D8.2(A) R63.1 R74.1 R75.1 R76.1 TP19.1 U2.22(GND2)
VCC2H_V: C39.2 C54.1 C55.1 C56.1 C57.1 D12.1(K) U2.24(VCC2)
VEE2H_V: C38.1 C56.2 C57.2 C58.2 C59.2 C60.2 Q2.2(S) R44.2 R65.1 U2.17(VEE2) U2.28(VEE2)
Vg_HS_V: C41.1 D11.1(K) D12.2(A) Q2.3(D) R47.2 R48.2 R50.2 R51.2 R54.2 R55.2 R58.2 R59.2 R61.2 R63.2 TP17.1
VHD_V: D7.1(CATHODE) D10.1(CATHODE)
ASC_EN_PRI: R60.1
ASCH_S_EN_V: C44.1 R70.1 R76.2 U2.18(ASC_EN_SEC)
ASCH_SEC_V: C43.1 R67.1 R75.2 U2.19(AI2(ASC_SEC))
DesatH_V: C33.1 D8.1(K) R42.1 TP14.1 U2.23(DESAT(CS))
GD0: R52.1
GD1: R53.1
GD2: R56.1
HS_DO_PWM_V: R43.1 TP16.1
nFLT1_HS_V: R40.1 R46.1
SDI_HS_V: C46.1 R69.2 U2.14(SDI)
SDO_HS_V: R72.1
SDO_LS_V: R69.1
SPI_CS: R73.1
SPI_SCLK: R66.1
VceclpH_V: C38.2 D9.2(ANODE) D11.2(A) R44.1 TP13.1 U2.32(VCECLP)
VclampH_V: R59.1 R62.2 TP12.1 U2.31(CLAMP)
VcpH_V: C39.1 U2.25(VCP)
VrefH_V: C40.1 TP15.1 U2.21(VREF)
VSUP_PRIM: R39.1 R40.2 R41.2 R57.2
NetC31_1: C31.1 C32.2 R39.2 U2.3(VCC1)
NetC34_2: C34.2 R43.2 U2.11(IN+)
NetC35_2: C35.2 R45.2 U2.10(IN-)
NetC36_2: C36.2 R46.2 U2.4(~{FLT1})
NetC37_2: C37.2 R49.2 U2.2(~{FLT2(DOUT)})
NetC42_1: C42.1 R71.1 U2.20(AI1)
NetC45_1: C45.1 R66.2 U2.12(SCLK)
NetC47_1: C47.1 R72.2 U2.15(SDO)
NetC48_1: C48.1 R73.2 U2.13(~{CS})
NetC49_1: C49.1 R60.2 U2.8(ASC_EN_PRI)
NetC50_1: C50.1 R64.2 U2.9(ASC_PRI)
NetC51_1: C51.1 R52.2 U2.5(GD0)
NetC52_1: C52.1 R53.2 U2.6(GD1)
NetC53_1: C53.1 R56.2 U2.7(GD2)
NetD7_2: D7.2(ANODE) R42.2
NetD9_1: D9.1(CATHODE) D10.2(ANODE)
NetQ2_1: Q2.1(G) R62.1 R65.2
NetR41_1: R41.1 R49.1
NetR47_1: R47.1 R48.1 U2.26(OUTH1)
NetR50_1: R50.1 R51.1 U2.27(OUTH2)
NetR54_1: R54.1 R55.1 U2.29(OUTL1)
NetR57_1: R57.1 R64.1 R68.2
NetR58_1: R58.1 R61.1 U2.30(OUTL2)
NetR67_2: R67.2 TP21.1
NetR70_2: R70.2 TP20.1

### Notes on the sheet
- Revision
- Revision History
- Notes
- A
- * first draft
- +15V
- -8V

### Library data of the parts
C31 = CMP-0007067-4: as C1 on sheet PMP31236RevA_HS_U
C32 C55 C56 C59 = CMP-0006356-2: as C2 on sheet PMP31236RevA_HS_U
C33-C37 C43 C44 C49-C53 = CMP-0006410-2: as C3 on sheet PMP31236RevA_HS_U
C38 C42 = CMP-0006324-2: as C8 on sheet PMP31236RevA_HS_U
C39 = CMP-0006356-2: as C9 on sheet PMP31236RevA_HS_U
C40 = CMP-0007067-4: as C10 on sheet PMP31236RevA_HS_U
C41 = CMP-0007725-2: as C11 on sheet PMP31236RevA_HS_U
C45-C48 = CMP-0860290-1: as C15 on sheet PMP31236RevA_HS_U
C54 C58 C60 = CMP-0008772-2: as C24 on sheet PMP31236RevA_HS_U
C57 = CMP-0007977-2: as C27 on sheet PMP31236RevA_HS_U
D7 = CMP-0095009-1: as D1 on sheet PMP31236RevA_HS_U
D8 D12 = CMP-0028458-1: as D2 on sheet PMP31236RevA_HS_U
D9 D10 = CMP-0095023-1: as D3 on sheet PMP31236RevA_HS_U
D11 = CMP-0028553-2: as D5 on sheet PMP31236RevA_HS_U
Q2 = CMP-0000739-1: as Q1 on sheet PMP31236RevA_HS_U
R39 = CMP-0026827-3: as R1 on sheet PMP31236RevA_HS_U
R40 R41 = CMP-0026935-3: as R2 on sheet PMP31236RevA_HS_U
R42 = CMP-0022109-5: as R4 on sheet PMP31236RevA_HS_U
R43 R45 R46 R49 R52 R53 R56 R60 R64 R66 R69 R72 R73 = CMP-0026824-2: as R5 on sheet PMP31236RevA_HS_U
R44 = CMP-0025787-4: as R6 on sheet PMP31236RevA_HS_U
R47 R48 = CMP-0020847-3: as R9 on sheet PMP31236RevA_HS_U
R50 R51 = CMP-0021481-3: as R12 on sheet PMP31236RevA_HS_U
R54 R55 = CMP-0021044-3: as R16 on sheet PMP31236RevA_HS_U
R57 R68 R75 R76 = CMP-0025958-3: as R19 on sheet PMP31236RevA_HS_U
R58 R61 = CMP-0020941-3: as R20 on sheet PMP31236RevA_HS_U
R59 R62 = CMP-0025697-4: as R21 on sheet PMP31236RevA_HS_U
R63 = CMP-0025701-4: as R25 on sheet PMP31236RevA_HS_U
R65 = CMP-0025701-4: as R27 on sheet PMP31236RevA_HS_U
R67 R70 = CMP-0025951-3: as R29 on sheet PMP31236RevA_HS_U
R71 = CMP-0026822-3: as R33 on sheet PMP31236RevA_HS_U
R74 = CMP-0026512-2: as R36 on sheet PMP31236RevA_HS_U
TP12-TP15 = CMP-0055139-1: as TP1 on sheet PMP31236RevA_HS_U
TP16-TP18 = CMP-0055137-1: as TP5 on sheet PMP31236RevA_HS_U
TP19 = CMP-0055138-1: as TP8 on sheet PMP31236RevA_HS_U
TP20 TP21 = CMP-0003825-1: 1mm Test Point, SMT; Manufacturer: Any
U2 = CMP-0093805-2: as U1 on sheet PMP31236RevA_HS_U

## Sheet PMP31236RevA_HS_W.SchDoc
size 431 x 279 mm; Date: Not shown in title block; ApprovedBy: Not shown in title block; CheckedBy: Not shown in title block; Author: Not shown in title block; CompanyName: Not shown in title block; Engineer: Not shown in title block; Organization: Not shown in title block; Address1: Not shown in title block; Address2: Not shown in title block; Address3: Not shown in title block; Address4: Not shown in title block; DocumentNumber: 3; Revision: Use project parameter SCH_Rev; SheetNumber: 3; SheetTotal: 11; PageSetup: Record=PageOptions¦CenterHorizontal=True¦CenterVertical=True¦PrintScale=1.00¦XCorrection=1.00¦YCorrection=1.00¦PrintKind=0¦BorderSize=5000000¦LeftOffset=0¦BottomOffset=0¦Orientation=2¦PaperLength=1000¦PaperWidth=1000¦Scale=100¦PaperSource=15¦PrintQuality=600¦MediaType=1¦DitherType=10¦PaperKind=Letter¦PrintScaleMode=1
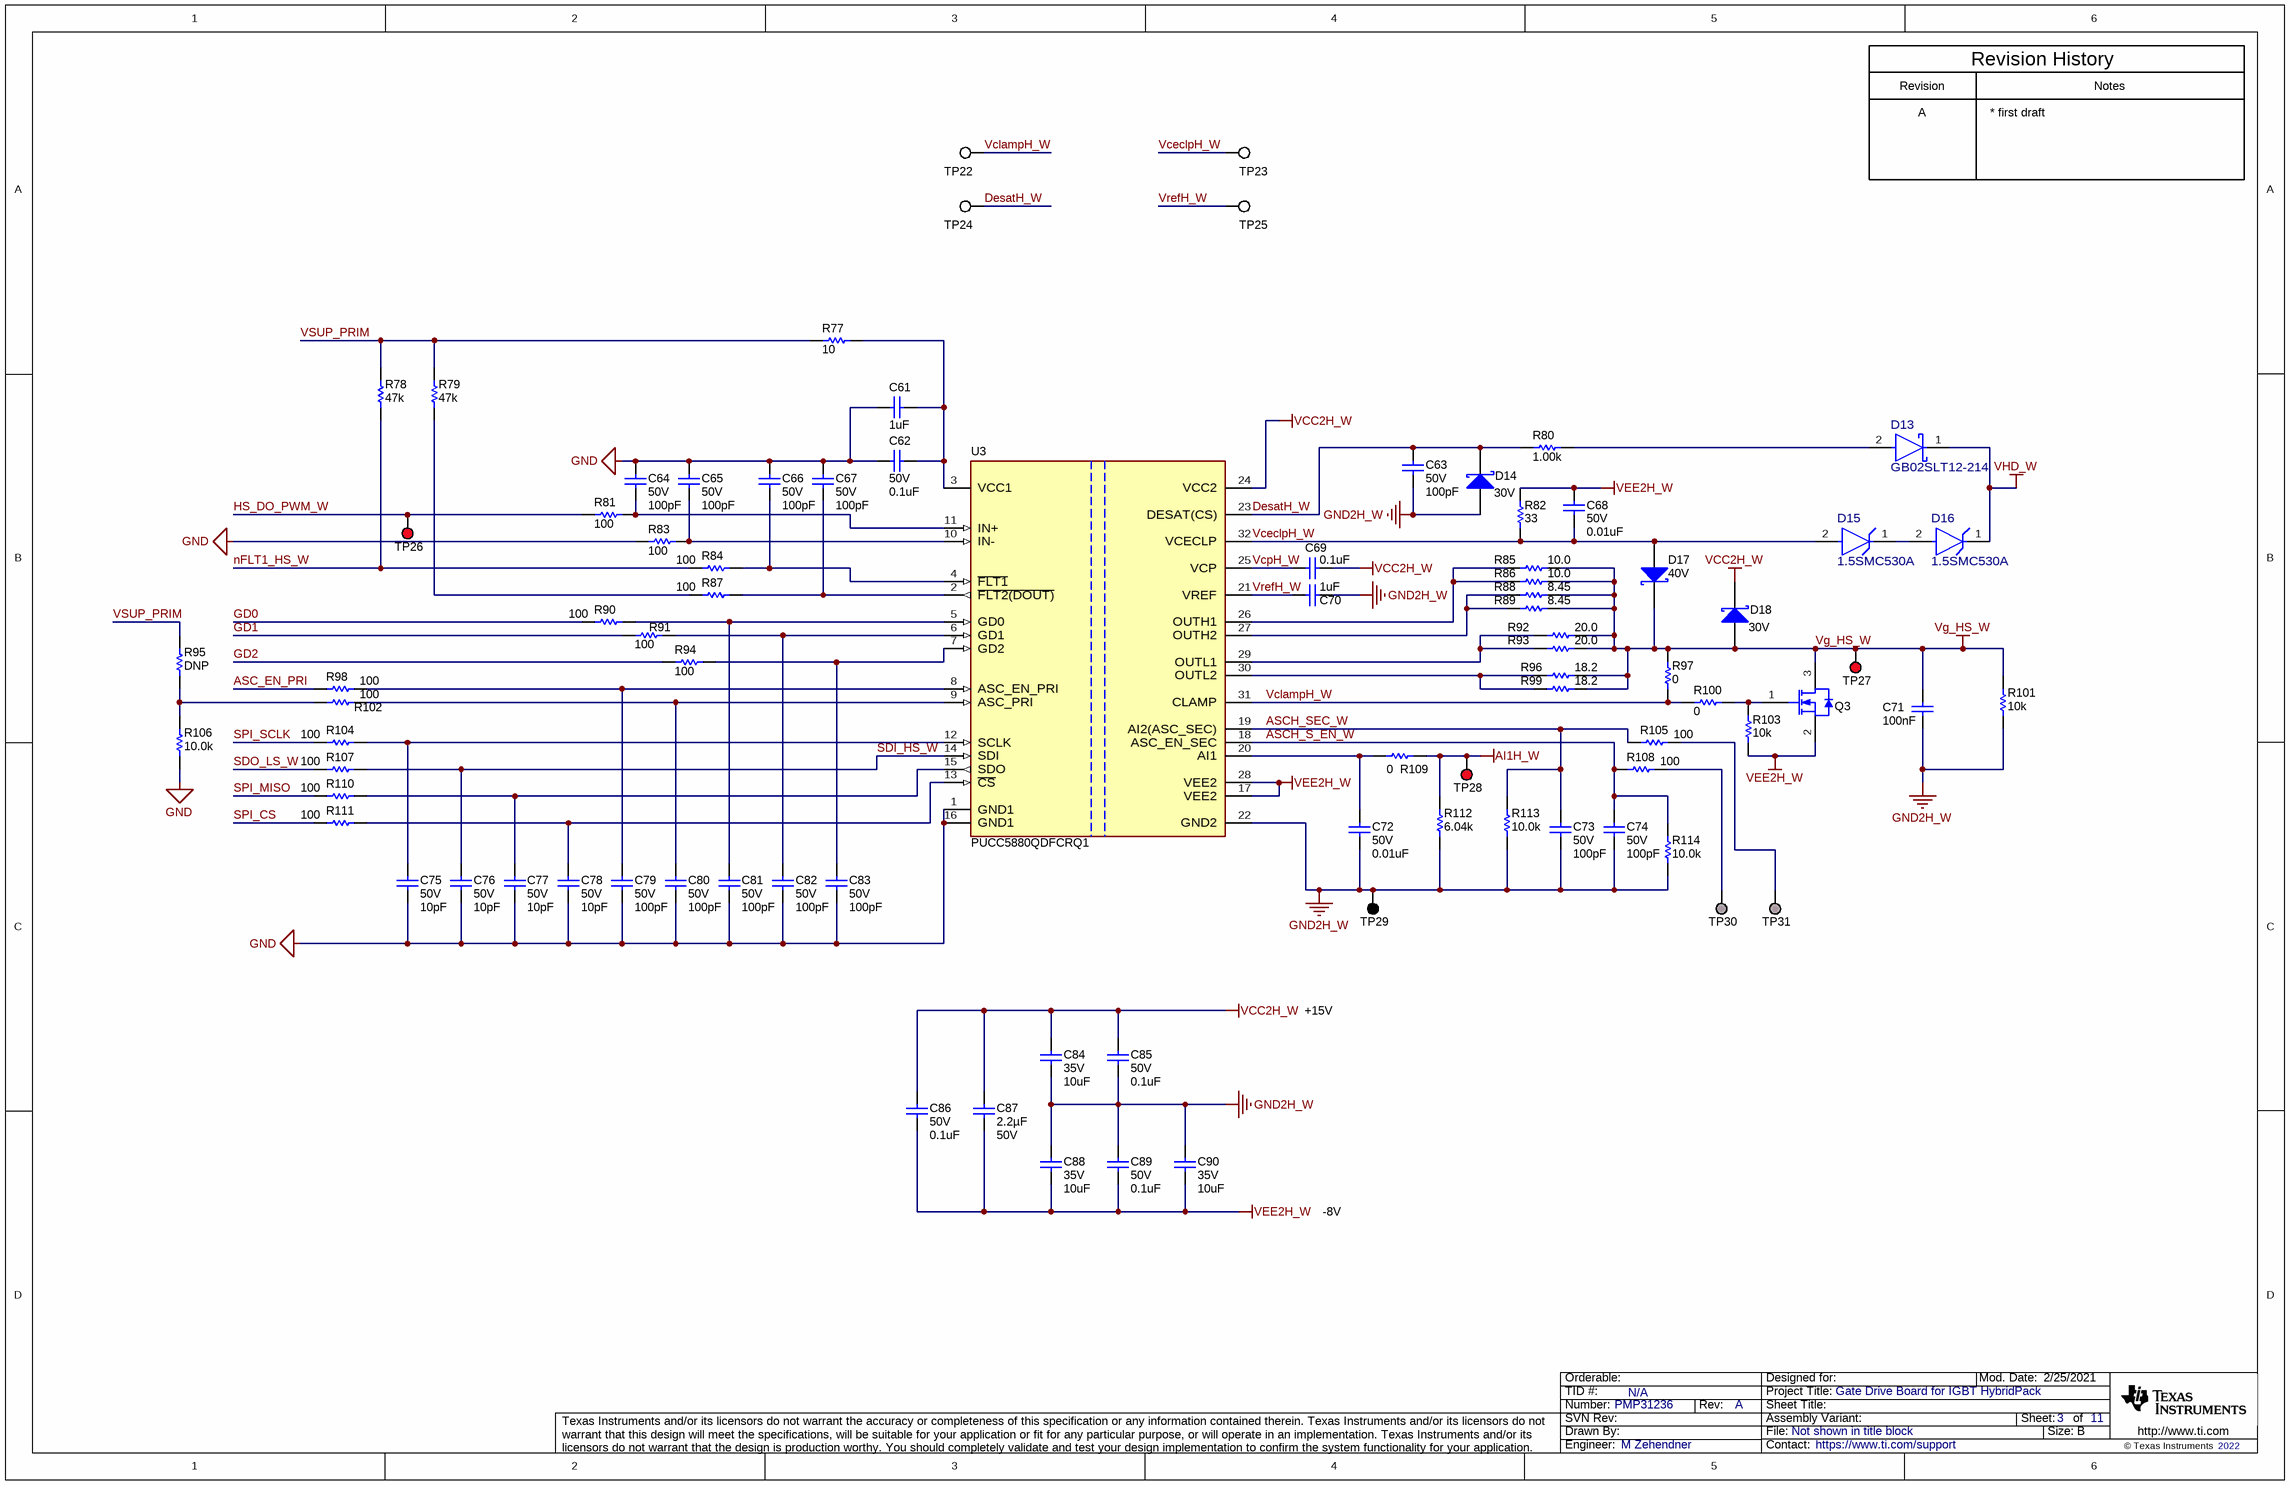
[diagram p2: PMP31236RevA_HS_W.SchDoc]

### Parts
C61  ValueDisplayed: 1uF  [0603]  (hidden comment: GRM21BR72A104KAC4L)
C62  VDC_V: 50V  ValueDisplayed: 0.1uF  [0402]  (hidden comment: GCM155R71H104KE02D)
C63  VDC_V: 50V  ValueDisplayed: 100pF  [0402]  (hidden comment: GRM1555C1H101JA01D)
C64  VDC_V: 50V  ValueDisplayed: 100pF  [0402]  (hidden comment: GRM1555C1H101JA01D)
C65  VDC_V: 50V  ValueDisplayed: 100pF  [0402]  (hidden comment: GRM1555C1H101JA01D)
C66  VDC_V: 50V  ValueDisplayed: 100pF  [0402]  (hidden comment: GRM1555C1H101JA01D)
C67  VDC_V: 50V  ValueDisplayed: 100pF  [0402]  (hidden comment: GRM1555C1H101JA01D)
C68  VDC_V: 50V  ValueDisplayed: 0.01uF  [0402]  (hidden comment: CGA2B3X7R1H103K050BB)
C69  ValueDisplayed: 0.1uF  [0402]  (hidden comment: GCM155R71H104KE02D)
C70  ValueDisplayed: 1uF  [0603]  (hidden comment: CGA3E1X7R1V105K080AC)
C71  Cap_F: 100nF  [0805_HV]  (hidden comment: C0805C104K5RACAUTO)
C72  VDC_V: 50V  ValueDisplayed: 0.01uF  [0402]  (hidden comment: CGA2B3X7R1H103K050BB)
C73  VDC_V: 50V  ValueDisplayed: 100pF  [0402]  (hidden comment: GRM1555C1H101JA01D)
C74  VDC_V: 50V  ValueDisplayed: 100pF  [0402]  (hidden comment: GRM1555C1H101JA01D)
C75  VDC_V: 50V  ValueDisplayed: 10pF  [0402]  (hidden comment: GCM1555C1H100JA16D)
C76  VDC_V: 50V  ValueDisplayed: 10pF  [0402]  (hidden comment: GCM1555C1H100JA16D)
C77  VDC_V: 50V  ValueDisplayed: 10pF  [0402]  (hidden comment: GCM1555C1H100JA16D)
C78  VDC_V: 50V  ValueDisplayed: 10pF  [0402]  (hidden comment: GCM1555C1H100JA16D)
C79  VDC_V: 50V  ValueDisplayed: 100pF  [0402]  (hidden comment: GRM1555C1H101JA01D)
C80  VDC_V: 50V  ValueDisplayed: 100pF  [0402]  (hidden comment: GRM1555C1H101JA01D)
C81  VDC_V: 50V  ValueDisplayed: 100pF  [0402]  (hidden comment: GRM1555C1H101JA01D)
C82  VDC_V: 50V  ValueDisplayed: 100pF  [0402]  (hidden comment: GRM1555C1H101JA01D)
C83  VDC_V: 50V  ValueDisplayed: 100pF  [0402]  (hidden comment: GRM1555C1H101JA01D)
C84  VDC_V: 35V  ValueDisplayed: 10uF  [1206_190]  (hidden comment: CGA5L1X7R1V106M160AC)
C85  VDC_V: 50V  ValueDisplayed: 0.1uF  [0402]  (hidden comment: GCM155R71H104KE02D)
C86  VDC_V: 50V  ValueDisplayed: 0.1uF  [0402]  (hidden comment: GCM155R71H104KE02D)
C87  Cap_F: 2.2µF  VDC_V: 50V  [0805_HV]  (hidden comment: CGA4J3X7R1H225K125AB)
C88  VDC_V: 35V  ValueDisplayed: 10uF  [1206_190]  (hidden comment: CGA5L1X7R1V106M160AC)
C89  VDC_V: 50V  ValueDisplayed: 0.1uF  [0402]  (hidden comment: GCM155R71H104KE02D)
C90  VDC_V: 35V  ValueDisplayed: 10uF  [1206_190]  (hidden comment: CGA5L1X7R1V106M160AC)
D13  GB02SLT12-214  [FP-GB02SLT12-214_DO-214AA-MFG]
D14  value 30V  [SOD-323]  (hidden comment: BAT54WS-7-F)
D15  1.5SMC530A  [FP-1.5SMC530A_SMC-MFG]
D16  1.5SMC530A  [FP-1.5SMC530A_SMC-MFG]
D17  value 40V  [SMA]  (hidden comment: MBRA340T3G)
D18  value 30V  [SOD-323]  (hidden comment: BAT54WS-7-F)
Q3  SI2318CDS-T1-GE3  [SOT-23]  (value not drawn)
R77  ValueDisplayed: 10  [0402]  (hidden comment: CRCW040210R0JNED)
R78  ValueDisplayed: 47k  [0402]  (hidden comment: CRCW040247K0JNED)
R79  ValueDisplayed: 47k  [0402]  (hidden comment: CRCW040247K0JNED)
R80  ValueDisplayed: 1.00k  [0603]  (hidden comment: CRCW06031K00FKEA)
R81  ValueDisplayed: 100  [0402]  (hidden comment: CRCW0402100RJNED)
R82  ValueDisplayed: 33  [0603]  (hidden comment: CRCW060333R0JNEA)
R83  ValueDisplayed: 100  [0402]  (hidden comment: CRCW0402100RJNED)
R84  ValueDisplayed: 100  [0402]  (hidden comment: CRCW0402100RJNED)
R85  ValueDisplayed: 10.0  [0805_HV]  (hidden comment: CRCW080510R0FKEA)
R86  ValueDisplayed: 10.0  [0805_HV]  (hidden comment: CRCW080510R0FKEA)
R87  ValueDisplayed: 100  [0402]  (hidden comment: CRCW0402100RJNED)
R88  ValueDisplayed: 8.45  [0805_HV]  (hidden comment: CRCW08058R45FKEA)
R89  ValueDisplayed: 8.45  [0805_HV]  (hidden comment: CRCW08058R45FKEA)
R90  ValueDisplayed: 100  [0402]  (hidden comment: CRCW0402100RJNED)
R91  ValueDisplayed: 100  [0402]  (hidden comment: CRCW0402100RJNED)
R92  ValueDisplayed: 20.0  [0805_HV]  (hidden comment: CRCW080520R0FKEA)
R93  ValueDisplayed: 20.0  [0805_HV]  (hidden comment: CRCW080520R0FKEA)
R94  ValueDisplayed: 100  [0402]  (hidden comment: CRCW0402100RJNED)
R95  ValueDisplayed: DNP  [0402]  (hidden comment: CRCW040210K0FKED)
R96  ValueDisplayed: 18.2  [0805_HV]  (hidden comment: CRCW080518R2FKEA)
R97  ValueDisplayed: 0  [0603]  (hidden comment: CRCW06030000Z0EA)
R98  ValueDisplayed: 100  [0402]  (hidden comment: CRCW0402100RJNED)
R99  ValueDisplayed: 18.2  [0805_HV]  (hidden comment: CRCW080518R2FKEA)
R100  ValueDisplayed: 0  [0603]  (hidden comment: CRCW06030000Z0EA)
R101  ValueDisplayed: 10k  [0603]  (hidden comment: CRCW060310K0JNEA)
R102  ValueDisplayed: 100  [0402]  (hidden comment: CRCW0402100RJNED)
R103  ValueDisplayed: 10k  [0603]  (hidden comment: CRCW060310K0JNEA)
R104  ValueDisplayed: 100  [0402]  (hidden comment: CRCW0402100RJNED)
R105  ValueDisplayed: 100  [0402]  (hidden comment: CRCW0402100RFKED)
R106  ValueDisplayed: 10.0k  [0402]  (hidden comment: CRCW040210K0FKED)
R107  ValueDisplayed: 100  [0402]  (hidden comment: CRCW0402100RJNED)
R108  ValueDisplayed: 100  [0402]  (hidden comment: CRCW0402100RFKED)
R109  ValueDisplayed: 0  [0402]  (hidden comment: CRCW04020000Z0ED)
R110  ValueDisplayed: 100  [0402]  (hidden comment: CRCW0402100RJNED)
R111  ValueDisplayed: 100  [0402]  (hidden comment: CRCW0402100RJNED)
R112  ValueDisplayed: 6.04k  [0402]  (hidden comment: CRCW04026K04FKED)
R113  ValueDisplayed: 10.0k  [0402]  (hidden comment: CRCW040210K0FKED)
R114  ValueDisplayed: 10.0k  [0402]  (hidden comment: CRCW040210K0FKED)
TP22  (no value)  [Keystone5002]
TP23  (no value)  [Keystone5002]
TP24  (no value)  [Keystone5002]
TP25  (no value)  [Keystone5002]
TP26  5000  [Keystone5000]  (value not drawn)
TP27  5000  [Keystone5000]  (value not drawn)
TP28  5000  [Keystone5000]  (value not drawn)
TP29  5001  [Keystone5001]  (value not drawn)
TP30  TP_SM_1MM  [TP_SM_1MM]  (value not drawn)  (no BOM)
TP31  TP_SM_1MM  [TP_SM_1MM]  (value not drawn)  (no BOM)
U3  PUCC5880QDFCRQ1  [DFC0032A-MFG]

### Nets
AI1H_W: R109.2 R112.2 TP28.1
GND: C61.2 C62.1 C64.1 C65.1 C66.1 C67.1 C75.2 C76.2 C77.2 C78.2 C79.2 C80.2 C81.2 C82.2 C83.2 R83.1 R106.1 U3.1(GND1) U3.16(GND1)
GND2H_W: C63.2 C70.2 C71.2 C72.2 C73.2 C74.2 C84.2 C85.2 C88.1 C89.1 C90.1 D14.2(A) R101.1 R112.1 R113.1 R114.1 TP29.1 U3.22(GND2)
VCC2H_W: C69.2 C84.1 C85.1 C86.1 C87.1 D18.1(K) U3.24(VCC2)
VEE2H_W: C68.1 C86.2 C87.2 C88.2 C89.2 C90.2 Q3.2(S) R82.2 R103.1 U3.17(VEE2) U3.28(VEE2)
Vg_HS_W: C71.1 D17.1(K) D18.2(A) Q3.3(D) R85.2 R86.2 R88.2 R89.2 R92.2 R93.2 R96.2 R97.2 R99.2 R101.2 TP27.1
VHD_W: D13.1(CATHODE) D16.1(CATHODE)
ASC_EN_PRI: R98.1
ASCH_S_EN_W: C74.1 R108.1 R114.2 U3.18(ASC_EN_SEC)
ASCH_SEC_W: C73.1 R105.1 R113.2 U3.19(AI2(ASC_SEC))
DesatH_W: C63.1 D14.1(K) R80.1 TP24.1 U3.23(DESAT(CS))
GD0: R90.1
GD1: R91.1
GD2: R94.1
HS_DO_PWM_W: R81.1 TP26.1
nFLT1_HS_W: R78.1 R84.1
SDI_HS_W: C76.1 R107.2 U3.14(SDI)
SDO_LS_W: R107.1
SPI_CS: R111.1
SPI_MISO: R110.1
SPI_SCLK: R104.1
VceclpH_W: C68.2 D15.2(ANODE) D17.2(A) R82.1 TP23.1 U3.32(VCECLP)
VclampH_W: R97.1 R100.2 TP22.1 U3.31(CLAMP)
VcpH_W: C69.1 U3.25(VCP)
VrefH_W: C70.1 TP25.1 U3.21(VREF)
VSUP_PRIM: R77.1 R78.2 R79.2 R95.2
NetC61_1: C61.1 C62.2 R77.2 U3.3(VCC1)
NetC64_2: C64.2 R81.2 U3.11(IN+)
NetC65_2: C65.2 R83.2 U3.10(IN-)
NetC66_2: C66.2 R84.2 U3.4(~{FLT1})
NetC67_2: C67.2 R87.2 U3.2(~{FLT2(DOUT)})
NetC72_1: C72.1 R109.1 U3.20(AI1)
NetC75_1: C75.1 R104.2 U3.12(SCLK)
NetC77_1: C77.1 R110.2 U3.15(SDO)
NetC78_1: C78.1 R111.2 U3.13(~{CS})
NetC79_1: C79.1 R98.2 U3.8(ASC_EN_PRI)
NetC80_1: C80.1 R102.2 U3.9(ASC_PRI)
NetC81_1: C81.1 R90.2 U3.5(GD0)
NetC82_1: C82.1 R91.2 U3.6(GD1)
NetC83_1: C83.1 R94.2 U3.7(GD2)
NetD13_2: D13.2(ANODE) R80.2
NetD15_1: D15.1(CATHODE) D16.2(ANODE)
NetQ3_1: Q3.1(G) R100.1 R103.2
NetR79_1: R79.1 R87.1
NetR85_1: R85.1 R86.1 U3.26(OUTH1)
NetR88_1: R88.1 R89.1 U3.27(OUTH2)
NetR92_1: R92.1 R93.1 U3.29(OUTL1)
NetR95_1: R95.1 R102.1 R106.2
NetR96_1: R96.1 R99.1 U3.30(OUTL2)
NetR105_2: R105.2 TP31.1
NetR108_2: R108.2 TP30.1

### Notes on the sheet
- Revision
- Revision History
- Notes
- A
- * first draft
- +15V
- -8V

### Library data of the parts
C61 = CMP-0007067-4: as C1 on sheet PMP31236RevA_HS_U
C62 C85 C86 C89 = CMP-0006356-2: as C2 on sheet PMP31236RevA_HS_U
C63-C67 C73 C74 C79-C83 = CMP-0006410-2: as C3 on sheet PMP31236RevA_HS_U
C68 C72 = CMP-0006324-2: as C8 on sheet PMP31236RevA_HS_U
C69 = CMP-0006356-2: as C9 on sheet PMP31236RevA_HS_U
C70 = CMP-0007067-4: as C10 on sheet PMP31236RevA_HS_U
C71 = CMP-0007725-2: as C11 on sheet PMP31236RevA_HS_U
C75-C78 = CMP-0860290-1: as C15 on sheet PMP31236RevA_HS_U
C84 C88 C90 = CMP-0008772-2: as C24 on sheet PMP31236RevA_HS_U
C87 = CMP-0007977-2: as C27 on sheet PMP31236RevA_HS_U
D13 = CMP-0095009-1: as D1 on sheet PMP31236RevA_HS_U
D14 D18 = CMP-0028458-1: as D2 on sheet PMP31236RevA_HS_U
D15 D16 = CMP-0095023-1: as D3 on sheet PMP31236RevA_HS_U
D17 = CMP-0028553-2: as D5 on sheet PMP31236RevA_HS_U
Q3 = CMP-0000739-1: as Q1 on sheet PMP31236RevA_HS_U
R77 = CMP-0026827-3: as R1 on sheet PMP31236RevA_HS_U
R78 R79 = CMP-0026935-3: as R2 on sheet PMP31236RevA_HS_U
R80 = CMP-0022109-5: as R4 on sheet PMP31236RevA_HS_U
R81 R83 R84 R87 R90 R91 R94 R98 R102 R104 R107 R110 R111 = CMP-0026824-2: as R5 on sheet PMP31236RevA_HS_U
R82 = CMP-0025787-4: as R6 on sheet PMP31236RevA_HS_U
R85 R86 = CMP-0020847-3: as R9 on sheet PMP31236RevA_HS_U
R88 R89 = CMP-0021481-3: as R12 on sheet PMP31236RevA_HS_U
R92 R93 = CMP-0021044-3: as R16 on sheet PMP31236RevA_HS_U
R95 R106 R113 R114 = CMP-0025958-3: as R19 on sheet PMP31236RevA_HS_U
R96 R99 = CMP-0020941-3: as R20 on sheet PMP31236RevA_HS_U
R97 R100 = CMP-0025697-4: as R21 on sheet PMP31236RevA_HS_U
R101 = CMP-0025701-4: as R25 on sheet PMP31236RevA_HS_U
R103 = CMP-0025701-4: as R27 on sheet PMP31236RevA_HS_U
R105 R108 = CMP-0025951-3: as R29 on sheet PMP31236RevA_HS_U
R109 = CMP-0026822-3: as R33 on sheet PMP31236RevA_HS_U
R112 = CMP-0026512-2: as R36 on sheet PMP31236RevA_HS_U
TP22-TP25 = CMP-0055139-1: as TP1 on sheet PMP31236RevA_HS_U
TP26-TP28 = CMP-0055137-1: as TP5 on sheet PMP31236RevA_HS_U
TP29 = CMP-0055138-1: as TP8 on sheet PMP31236RevA_HS_U
TP30 TP31 = CMP-0003825-1: 1mm Test Point, SMT; Manufacturer: Any
U3 = CMP-0093805-2: as U1 on sheet PMP31236RevA_HS_U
